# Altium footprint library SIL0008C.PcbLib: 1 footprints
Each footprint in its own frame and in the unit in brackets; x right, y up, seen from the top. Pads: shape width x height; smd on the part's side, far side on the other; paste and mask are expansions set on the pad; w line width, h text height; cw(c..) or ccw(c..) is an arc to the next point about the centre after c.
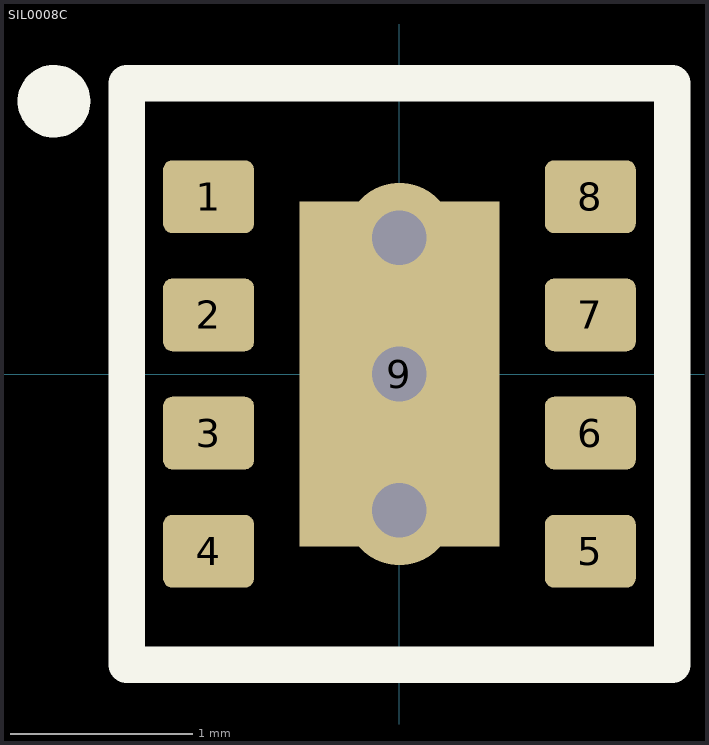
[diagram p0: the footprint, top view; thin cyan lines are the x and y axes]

## SIL0008C [mm]
pads (9):
  rrect25% 0.5x0.4 smd mask+0.05: 1(-1.05,0.975) 2(-1.05,0.325) 3(-1.05,-0.325) 4(-1.05,-0.975) 5(1.05,-0.975) 6(1.05,-0.325) 7(1.05,0.325) 8(1.05,0.975)
  rect 1.1x1.9 smd mask+0.05: 9(0,0)
via 0,-0.75 diameter 0.6 hole 0.3
via 0,0.75 diameter 0.6 hole 0.3
via 0,0 diameter 0.6 hole 0.3
Top Overlay:
  circle w0.2: c-1.9,1.5 r0.1
  lines w0.2: -1.5,-1.6 -1.5,1.6 1.5,1.6 1.5,-1.6 -1.5,-1.6
3D body "SIL0008D.stp": height 1.31, standoff 0, extent -1.4,-1.5 1.4,1.5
